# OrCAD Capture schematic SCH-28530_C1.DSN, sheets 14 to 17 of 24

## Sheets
14 14 EC1 PHY: size C
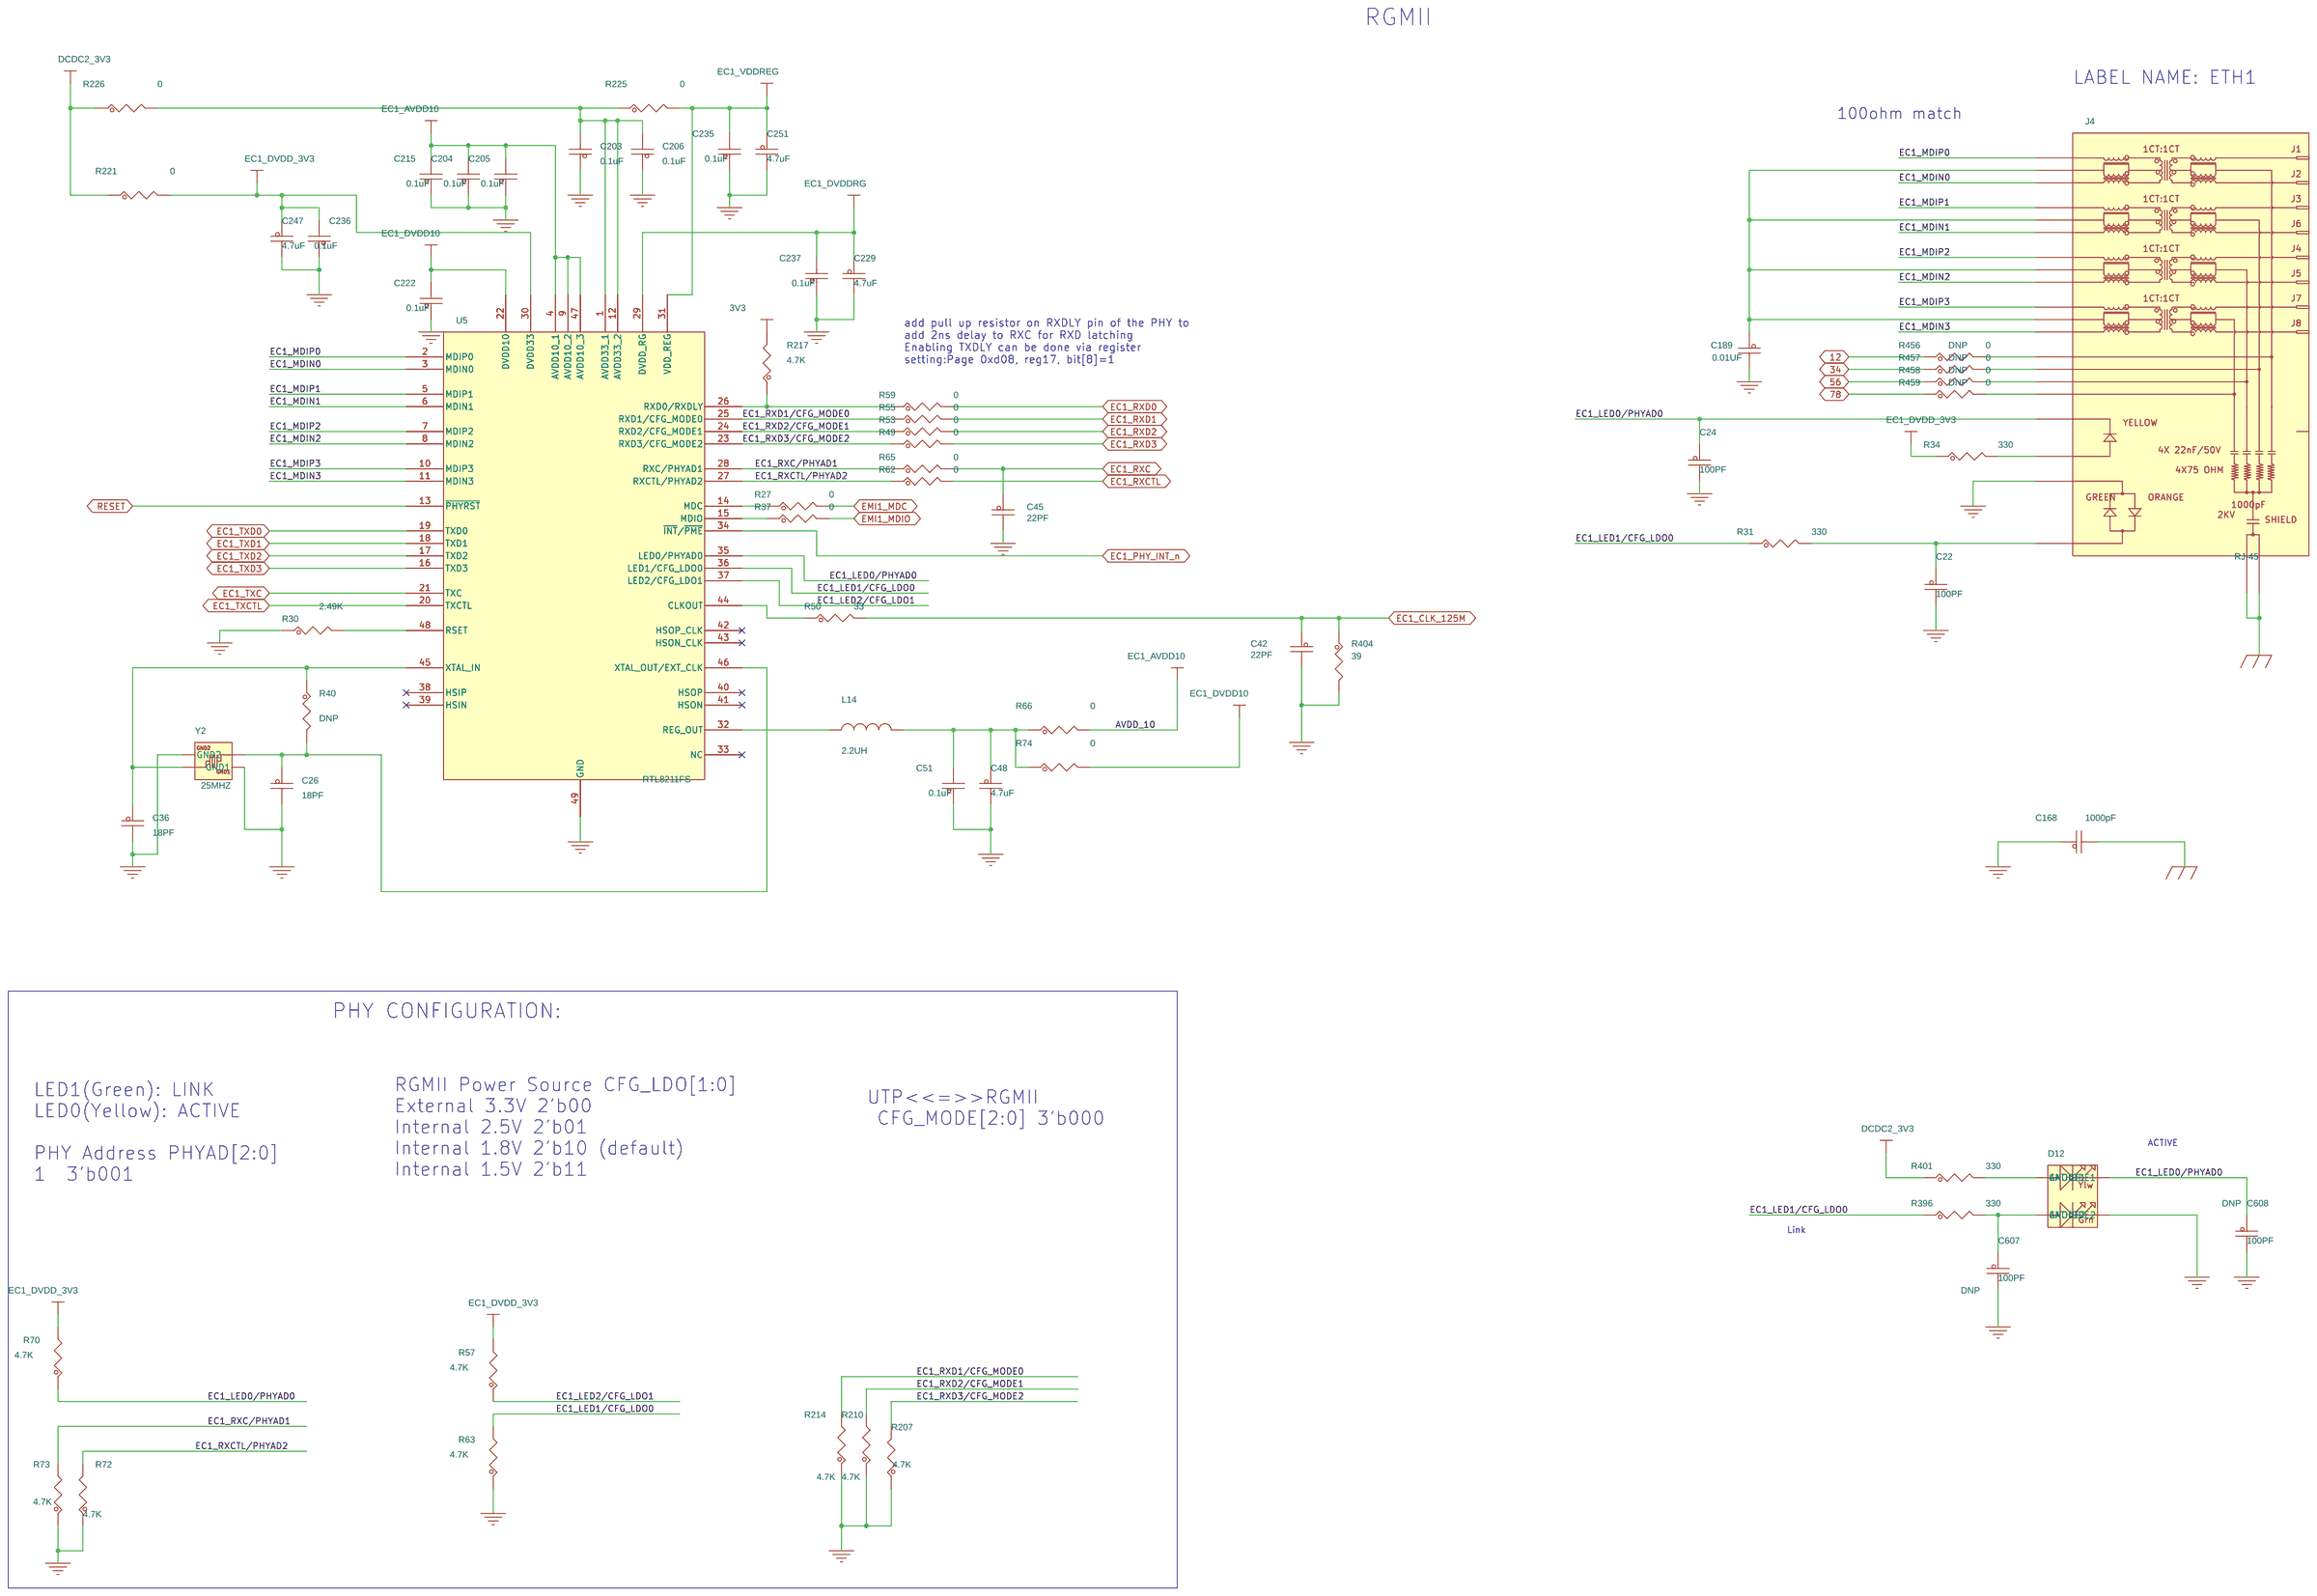
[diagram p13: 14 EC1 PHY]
15 15 SGMII PHY: size C
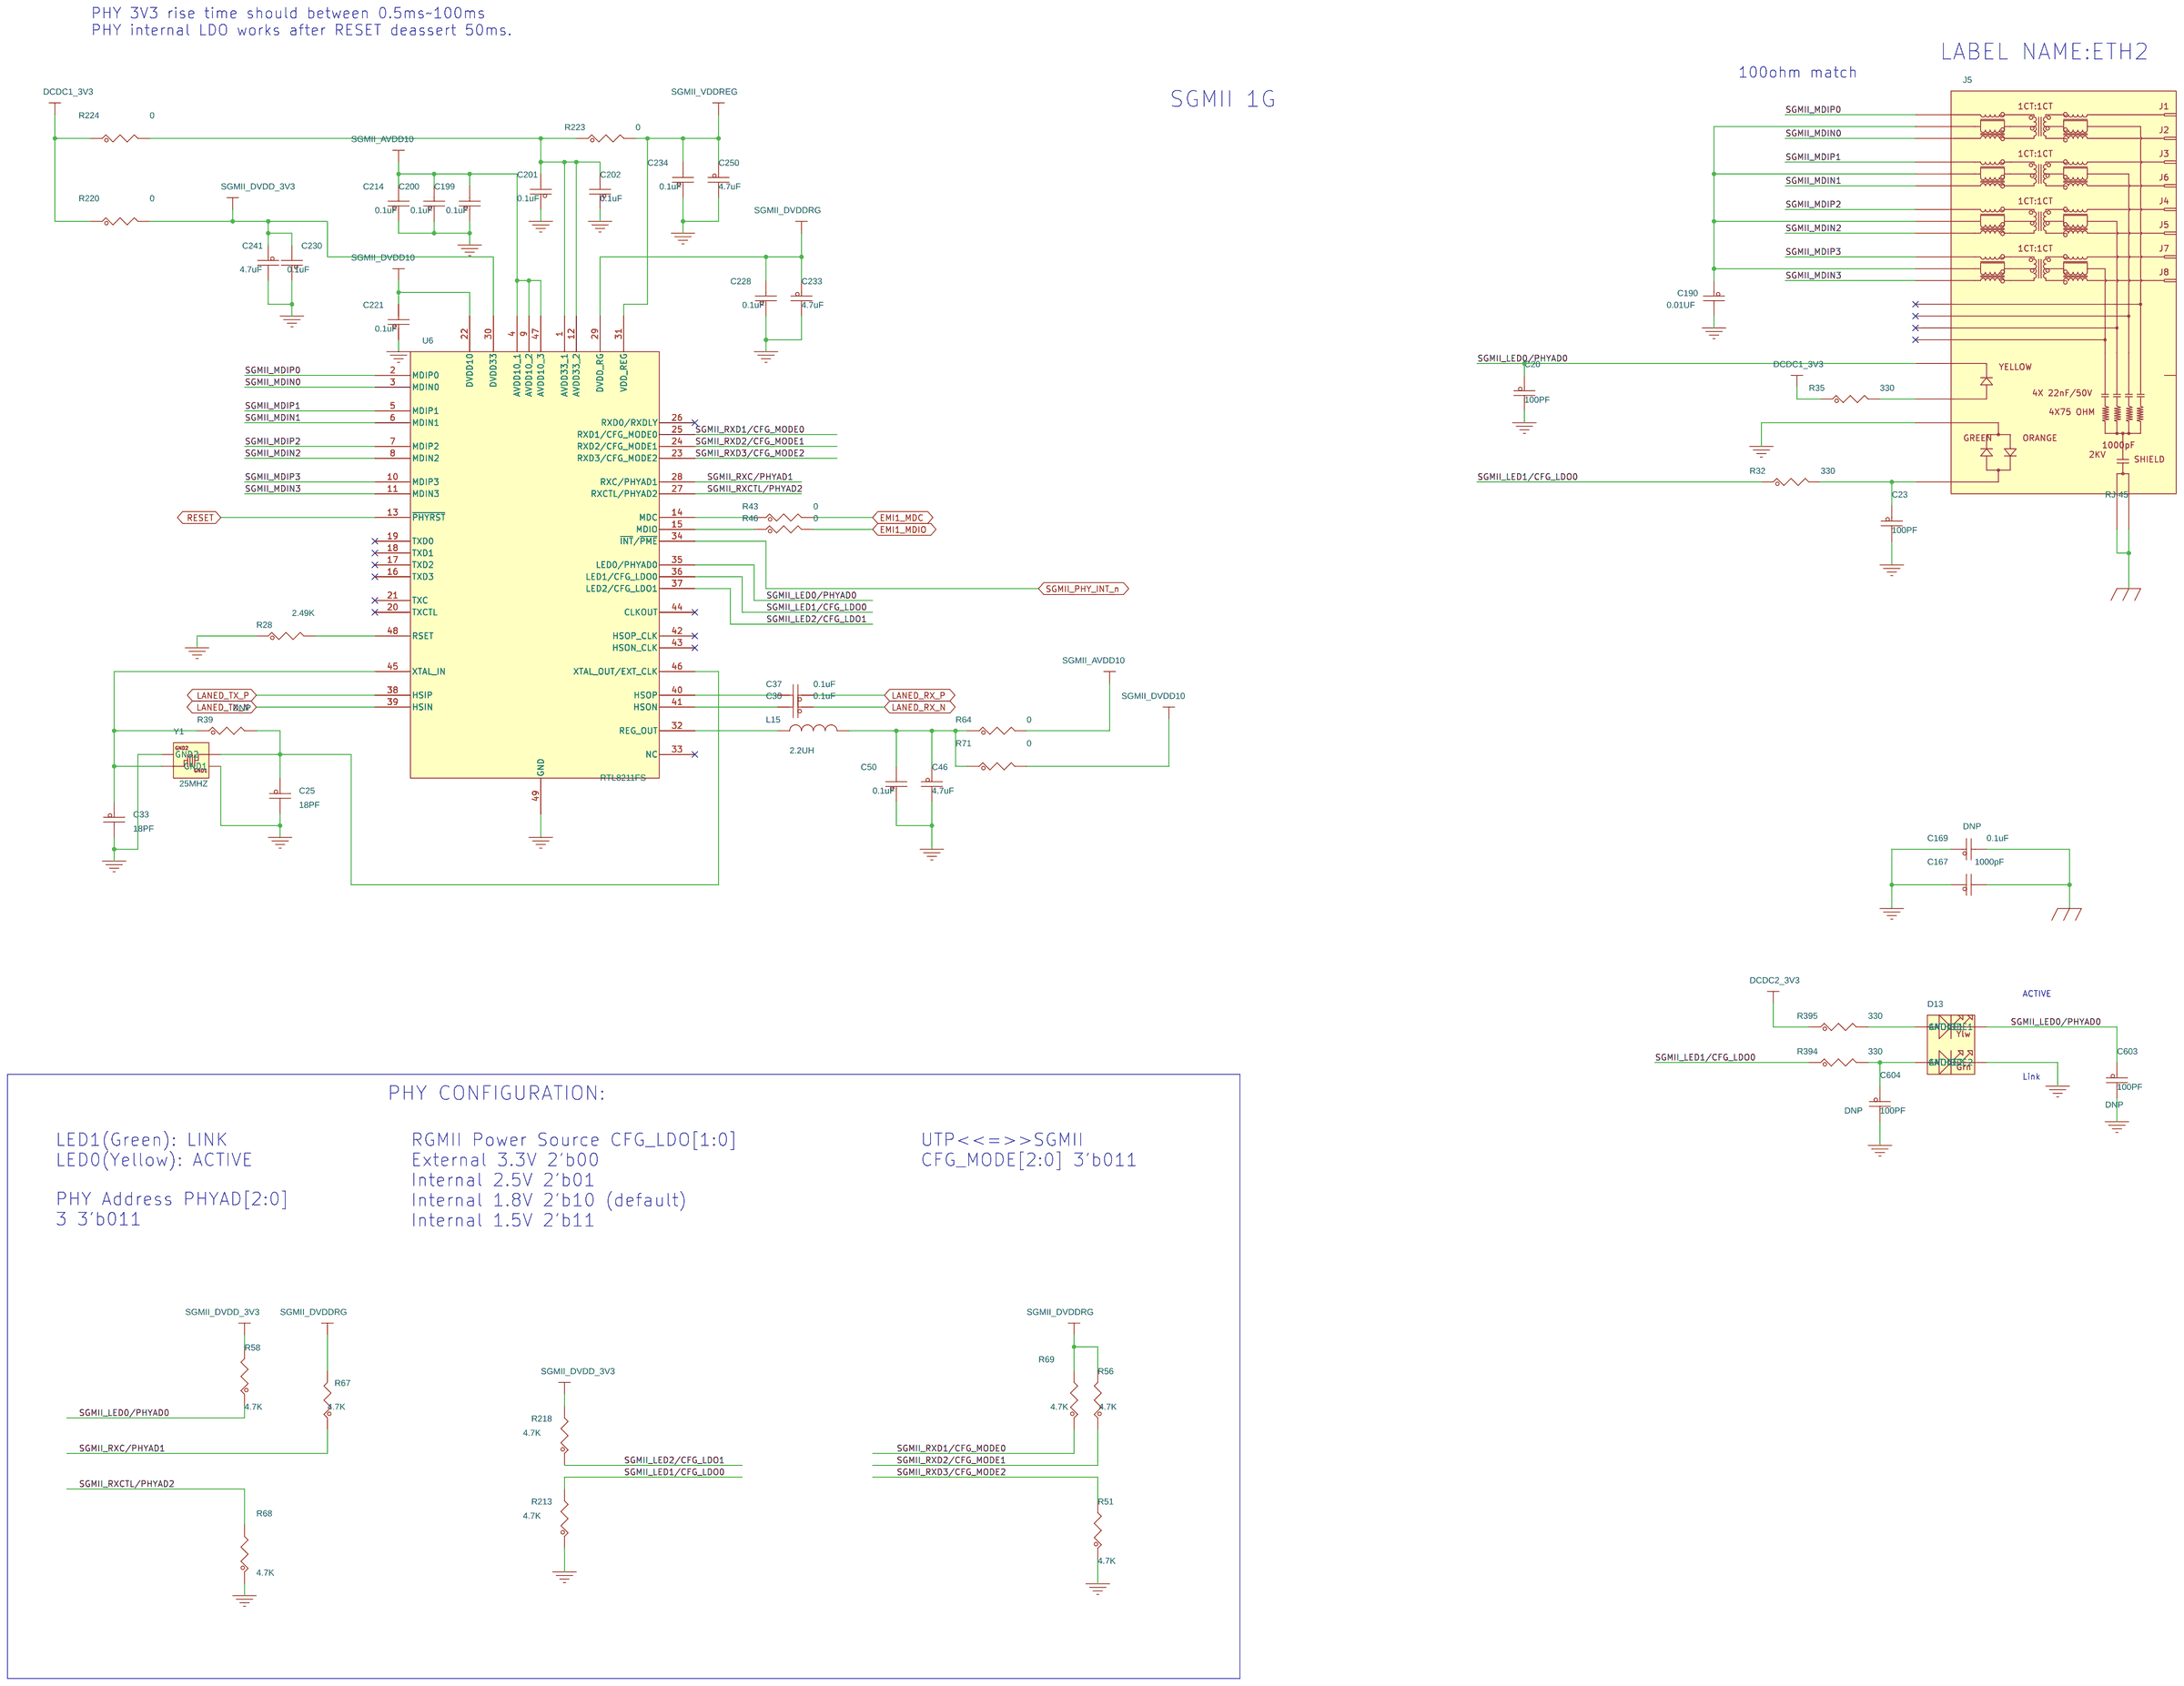
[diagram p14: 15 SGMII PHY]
16 16 AQR105: size C
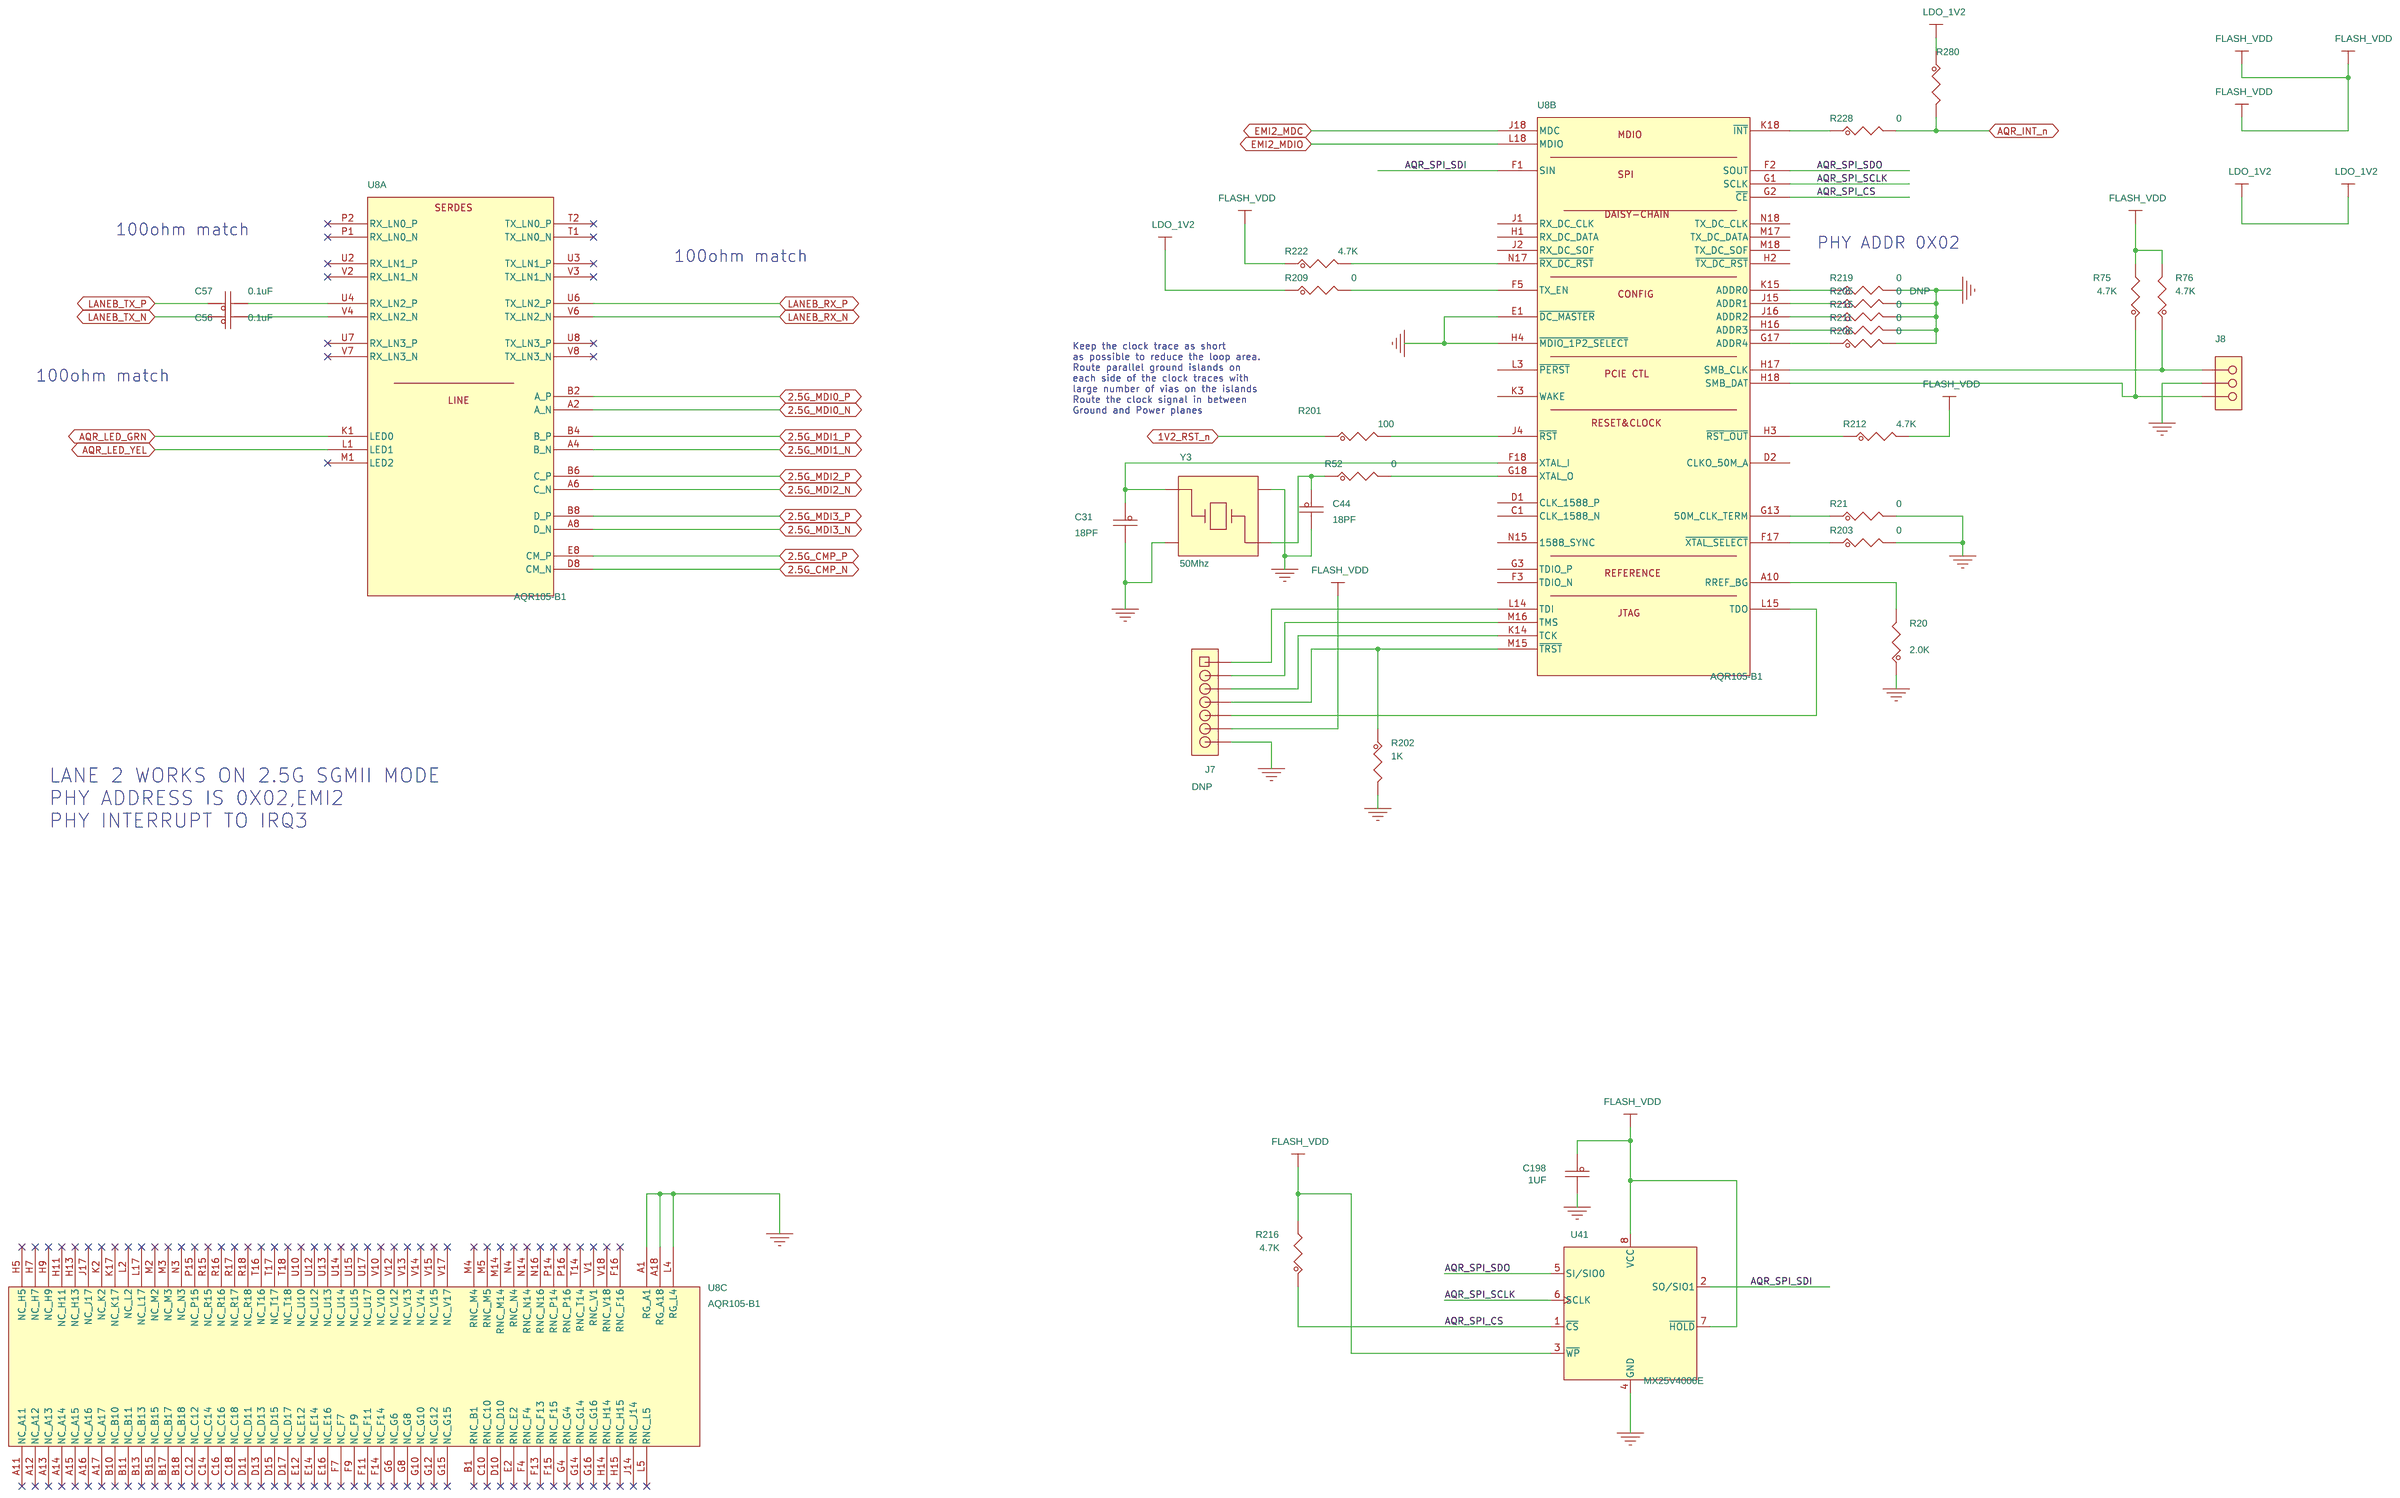
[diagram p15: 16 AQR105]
17 17 AQR105 POWER: size C
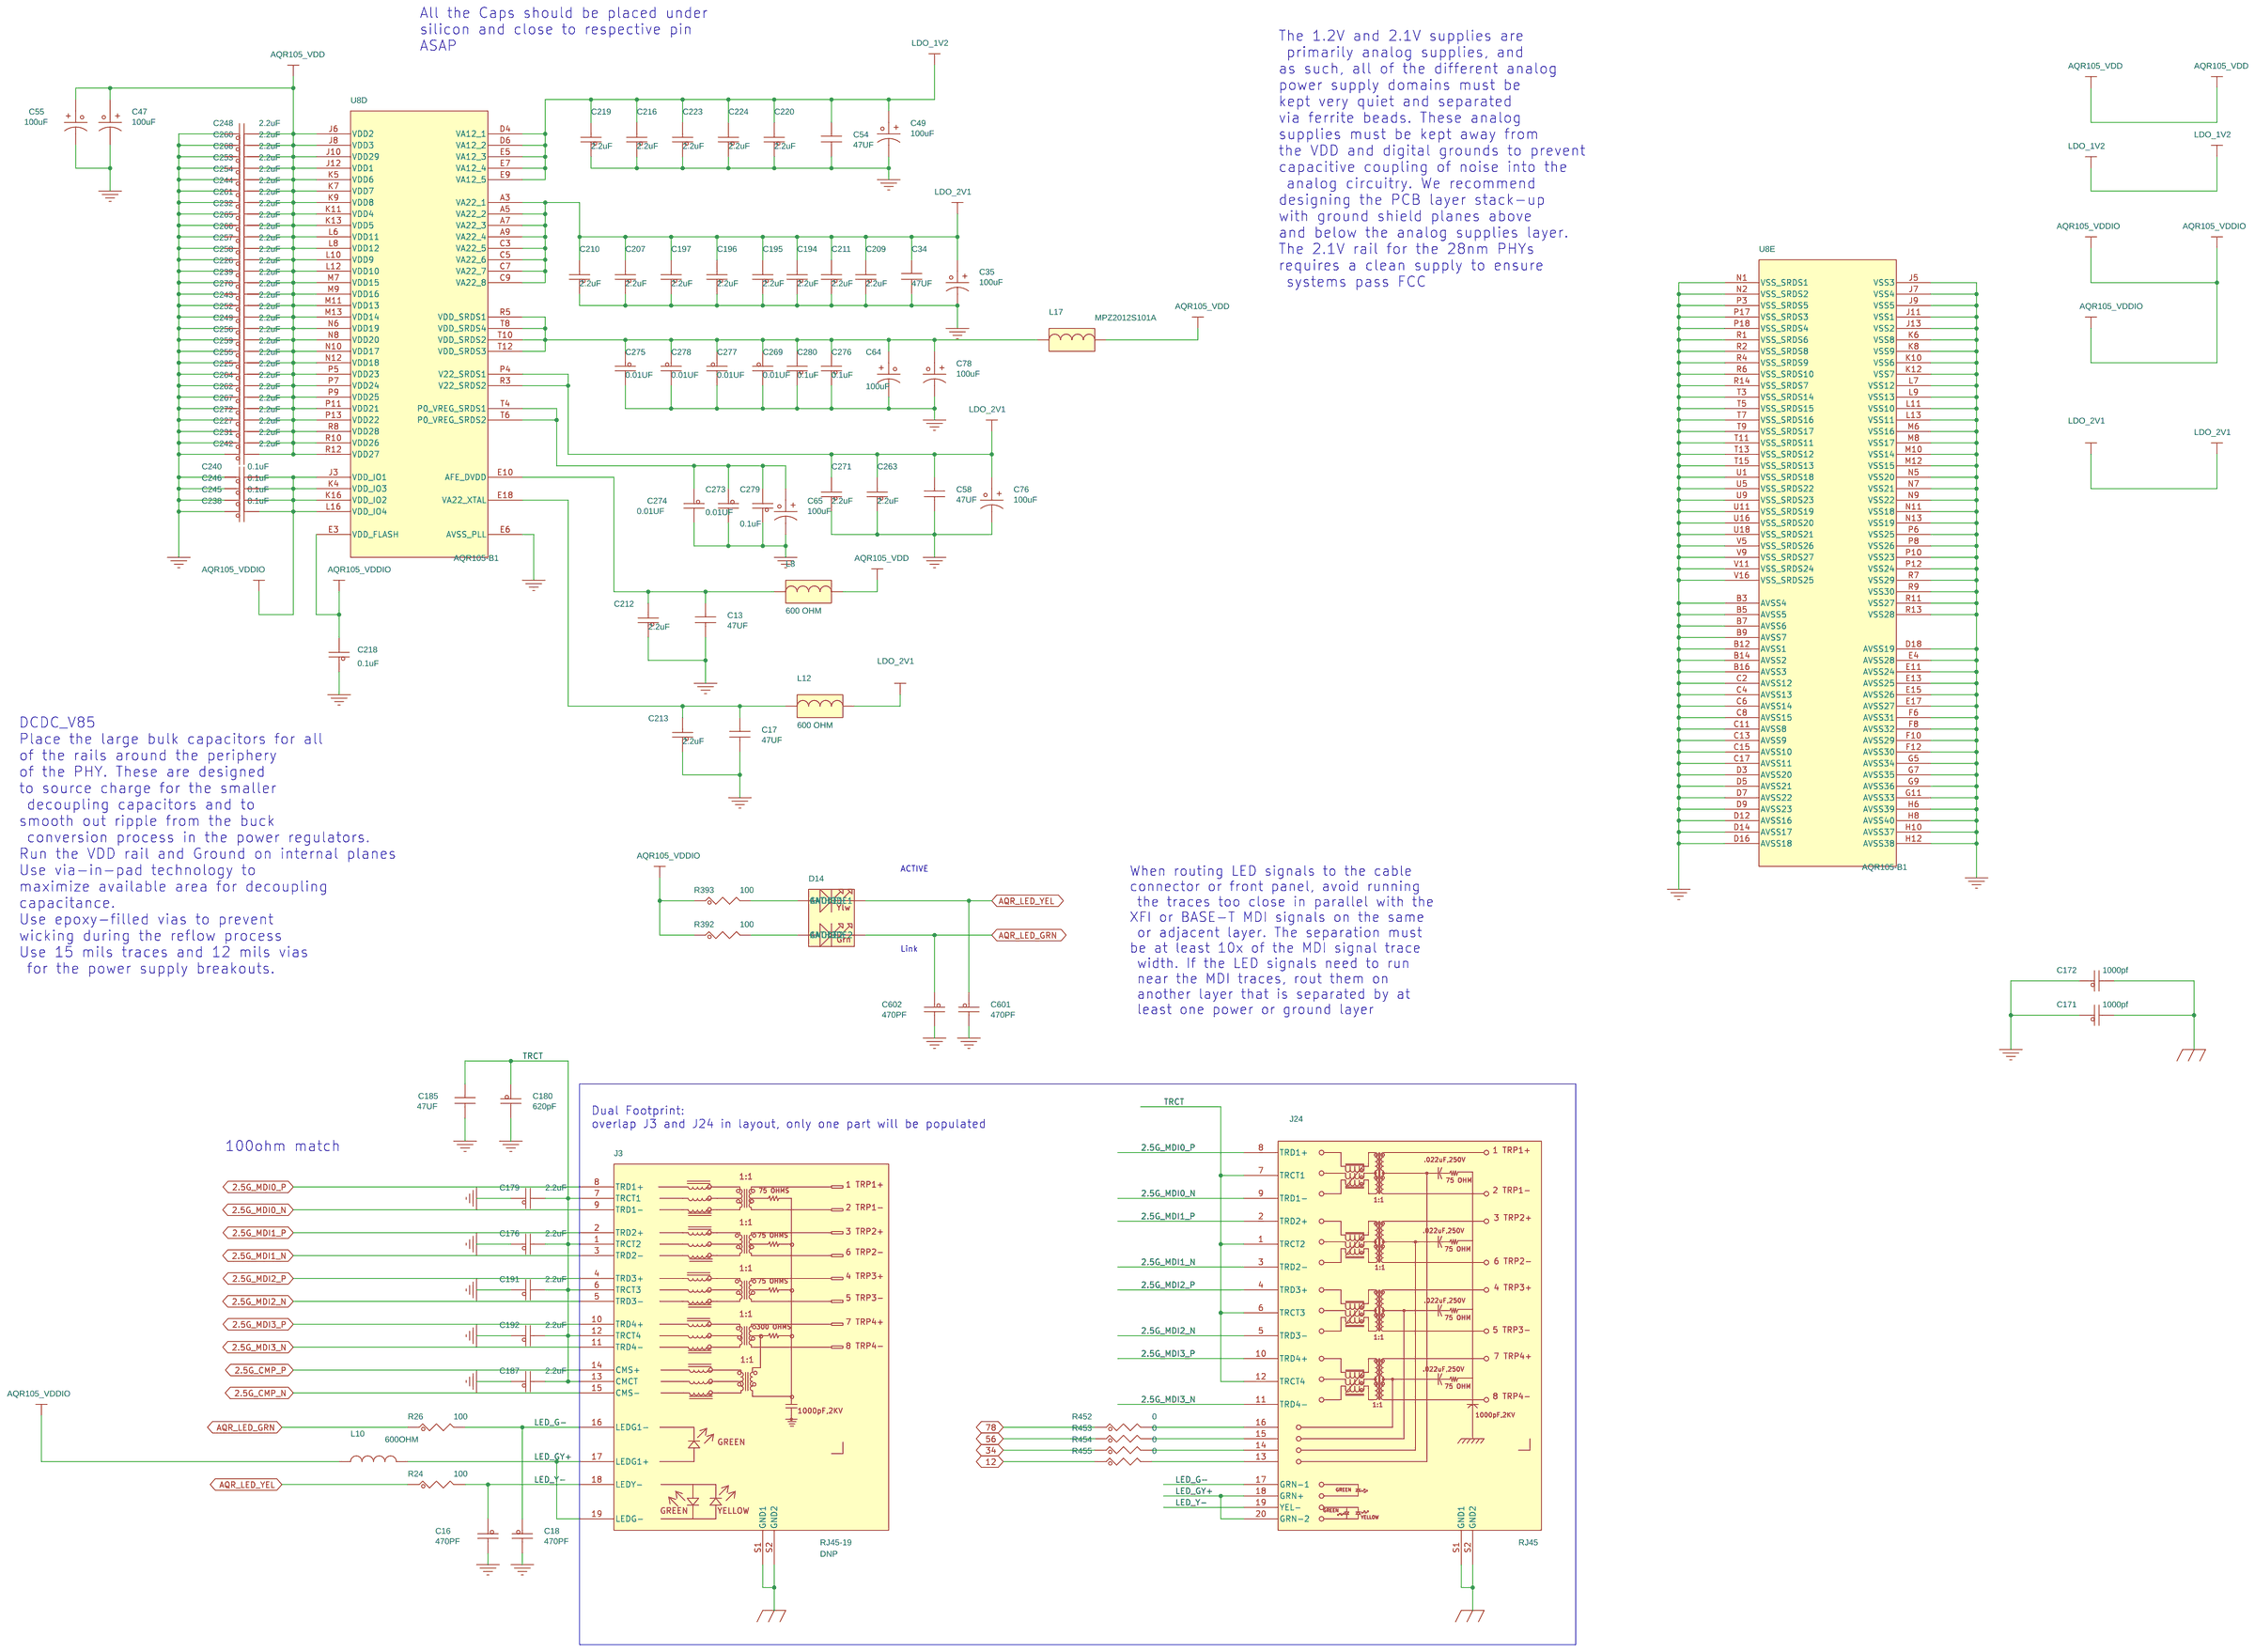
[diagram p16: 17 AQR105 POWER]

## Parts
sheet 14 EC1 PHY
C22  100PF  [CC0603_OV]
C24  100PF  [CC0603_OV]
C26  18PF  [CC0603_OV]
C36  18PF  [CC0603_OV]
C42  22PF  [CC0402_25]
C45  22PF  [CC0402_25]
C48  4.7uF  [CC0603_OV]
C51  0.1uF  [CC0402_25]
C168  1000pF  [cc1808_a]
C189  0.01UF  [CC0402_25]
C203  0.1uF  [CC0402_25]
C204  0.1uF  [CC0402_25]
C205  0.1uF  [CC0402_25]
C206  0.1uF  [CC0402_25]
C215  0.1uF  [CC0402_25]
C222  0.1uF  [CC0402_25]
C229  4.7uF  [CC0603_OV]
C235  0.1uF  [CC0402_25]
C236  0.1uF  [CC0402_25]
C237  0.1uF  [CC0402_25]
C247  4.7uF  [CC0603_OV]
C251  4.7uF  [CC0603_OV]
C607  100PF  [CC0603_OV]
C608  100PF  [CC0603_OV]
D12  LED GRN/YLW  [led4_2p54_9p3x4p5mm]
J4  RJ-45  [con_rj45_led_20_th]
L14  2.2UH  [IND2_4P3X4P3]
R27  0  [RC0603_OV]
R30  2.49K  [RC0603_OV]
R31  330  [RC0603_OV]
R34  330  [RC0603_OV]
R37  0  [RC0603_OV]
R40  1.0M  [RC0603_OV]
R49  0  [RC0402_25]
R50  33  [RC0603_OV]
R53  0  [RC0402_25]
R55  0  [RC0402_25]
R57  4.7K  [RC0603_OV]
R59  0  [RC0402_25]
R62  0  [RC0402_25]
R63  4.7K  [RC0603_OV]
R65  0  [RC0402_25]
R66  0  [RC0603_OV]
R70  4.7K  [RC0603_OV]
R72  4.7K  [RC0603_OV]
R73  4.7K  [RC0603_OV]
R74  0  [RC0603_OV]
R207  4.7K  [RC0603_OV]
R210  4.7K  [RC0603_OV]
R214  4.7K  [RC0603_OV]
R217  4.7K  [RC0603_OV]
R221  0  [RC0603_OV]
R225  0  [RC0603_OV]
R226  0  [RC0603_OV]
R396  330  [RC0603_OV]
R401  330  [RC0603_OV]
R404  39  [RC0402_25]
R456  0  [RC0603_OV]
R457  0  [RC0603_OV]
R458  0  [RC0603_OV]
R459  0  [RC0603_OV]
U5  RTL8211FS  [qfn_48_0p4_6x6mm]
Y2  25MHZ  [xtlosc4_3p2x2p5mm_sm]
sheet 15 SGMII PHY
C20  100PF  [CC0603_OV]
C23  100PF  [CC0603_OV]
C25  18PF  [CC0603_OV]
C30  0.1uF  [CC0402_25]
C33  18PF  [CC0603_OV]
C37  0.1uF  [CC0402_25]
C46  4.7uF  [CC0603_OV]
C50  0.1uF  [CC0402_25]
C167  1000pF  [cc1808_a]
C169  0.1uF  [cc1812]
C190  0.01UF  [CC0402_25]
C199  0.1uF  [CC0402_25]
C200  0.1uF  [CC0402_25]
C201  0.1uF  [CC0402_25]
C202  0.1uF  [CC0402_25]
C214  0.1uF  [CC0402_25]
C221  0.1uF  [CC0402_25]
C228  0.1uF  [CC0402_25]
C230  0.1uF  [CC0402_25]
C233  4.7uF  [CC0603_OV]
C234  0.1uF  [CC0402_25]
C241  4.7uF  [CC0603_OV]
C250  4.7uF  [CC0603_OV]
C603  100PF  [CC0603_OV]
C604  100PF  [CC0603_OV]
D13  LED GRN/YLW  [led4_2p54_9p3x4p5mm]
J5  RJ-45  [con_rj45_led_20_th]
L15  2.2UH  [IND2_4P3X4P3]
R28  2.49K  [RC0603_OV]
R32  330  [RC0603_OV]
R35  330  [RC0603_OV]
R39  1.0M  [RC0603_OV]
R43  0  [RC0603_OV]
R46  0  [RC0603_OV]
R51  4.7K  [RC0603_OV]
R56  4.7K  [RC0603_OV]
R58  4.7K  [RC0603_OV]
R64  0  [RC0603_OV]
R67  4.7K  [RC0603_OV]
R68  4.7K  [RC0603_OV]
R69  4.7K  [RC0603_OV]
R71  0  [RC0603_OV]
R213  4.7K  [RC0603_OV]
R218  4.7K  [RC0603_OV]
R220  0  [RC0603_OV]
R223  0  [RC0603_OV]
R224  0  [RC0603_OV]
R394  330  [RC0603_OV]
R395  330  [RC0603_OV]
U6  RTL8211FS  [qfn_48_0p4_6x6mm]
Y1  25MHZ  [xtlosc4_3p2x2p5mm_sm]
sheet 16 AQR105
C31  18PF  [CC0603_OV]
C44  18PF  [CC0603_OV]
C56  0.1uF  [CC0402_25]
C57  0.1uF  [CC0402_25]
C198  1UF  [CC0402_25]
J7  HDR_1X7  [JUMP1X7-6040]
J8  HDR TH 1X3  [HDR103]
R20  2.0K  [RC0603_OV]
R21  0  [RC0603_OV]
R52  0  [RC0603_OV]
R75  4.7K  [RC0603_OV]
R76  4.7K  [RC0603_OV]
R201  100  [RC0603_OV]
R202  1K  [RC0603_OV]
R203  0  [RC0603_OV]
R205  0  [RC0603_OV]
R206  0  [RC0603_OV]
R209  0  [RC0603_OV]
R211  0  [RC0603_OV]
R212  4.7K  [RC0603_OV]
R215  0  [RC0603_OV]
R216  4.7K  [RC0603_OV]
R219  0  [RC0603_OV]
R222  4.7K  [RC0603_OV]
R228  0  [RC0603_OV]
R280  4.7K  [RC0402_25]
U41  MX25V4006E  [SO8_1p27_4x5]
Y3  50Mhz  [xtal4_3p3x2p6_sm_fl]
sheet 17 AQR105 POWER
C13  47UF  [CC1210]
C16  470PF  [CC0603_OV]
C17  47UF  [CC1210]
C18  470PF  [CC0603_OV]
C34  47UF  [CC1210]
C35  100uF  [cce63x55]
C47  100uF  [cce63x55]
C49  100uF  [cce63x55]
C54  47UF  [CC1210]
C55  100uF  [cce63x55]
C58  47UF  [CC1210]
C64  100uF  [cce63x55]
C65  100uF  [cce63x55]
C76  100uF  [cce63x55]
C78  100uF  [cce63x55]
C171  1000pf  [CC1210]
C172  1000pf  [CC1210]
C176  2.2uF  [CC0402_25]
C179  2.2uF  [CC0402_25]
C180  620pF  [CC0402_25]
C185  47UF  [CC1210]
C187  2.2uF  [CC0402_25]
C191  2.2uF  [CC0402_25]
C192  2.2uF  [CC0402_25]
C194  2.2uF  [CC0402_25]
C195  2.2uF  [CC0402_25]
C196  2.2uF  [CC0402_25]
C197  2.2uF  [CC0402_25]
C207  2.2uF  [CC0402_25]
C209  2.2uF  [CC0402_25]
C210  2.2uF  [CC0402_25]
C211  2.2uF  [CC0402_25]
C212  2.2uF  [CC0402_25]
C213  2.2uF  [CC0402_25]
C216  2.2uF  [CC0402_25]
C218  0.1uF  [CC0402_25]
C219  2.2uF  [CC0402_25]
C220  2.2uF  [CC0402_25]
C223  2.2uF  [CC0402_25]
C224  2.2uF  [CC0402_25]
C225  2.2uF  [CC0402_25]
C226  2.2uF  [CC0402_25]
C227  2.2uF  [CC0402_25]
C231  2.2uF  [CC0402_25]
C232  2.2uF  [CC0402_25]
C238  0.1uF  [CC0402_25]
C239  2.2uF  [CC0402_25]
C240  0.1uF  [CC0402_25]
C242  2.2uF  [CC0402_25]
C243  2.2uF  [CC0402_25]
C244  2.2uF  [CC0402_25]
C245  0.1uF  [CC0402_25]
C246  0.1uF  [CC0402_25]
C248  2.2uF  [CC0402_25]
C249  2.2uF  [CC0402_25]
C252  2.2uF  [CC0402_25]
C253  2.2uF  [CC0402_25]
C254  2.2uF  [CC0402_25]
C255  2.2uF  [CC0402_25]
C256  2.2uF  [CC0402_25]
C257  2.2uF  [CC0402_25]
C258  2.2uF  [CC0402_25]
C259  2.2uF  [CC0402_25]
C260  2.2uF  [CC0402_25]
C261  2.2uF  [CC0402_25]
C262  2.2uF  [CC0402_25]
C263  2.2uF  [CC0402_25]
C264  2.2uF  [CC0402_25]
C265  2.2uF  [CC0402_25]
C266  2.2uF  [CC0402_25]
C267  2.2uF  [CC0402_25]
C268  2.2uF  [CC0402_25]
C269  0.01UF  [CC0402_25]
C270  2.2uF  [CC0402_25]
C271  2.2uF  [CC0402_25]
C272  2.2uF  [CC0402_25]
C273  0.01UF  [CC0402_25]
C274  0.01UF  [CC0402_25]
C275  0.01UF  [CC0402_25]
C276  0.1uF  [CC0402_25]
C277  0.01UF  [CC0402_25]
C278  0.01UF  [CC0402_25]
C279  0.1uF  [CC0402_25]
C280  0.1uF  [CC0402_25]
C601  470PF  [CC0603_OV]
C602  470PF  [CC0603_OV]
D14  LED GRN/YLW  [led4_2p54_9p3x4p5mm]
J3  RJ45-19  [con19_rj-45_led_80mil_th_ra]
J24  RJ45  [con16_rj45_led_80_th_ra]
L8  600 OHM  [IND_0805]
L10  600OHM  [IND_0603]
L12  600 OHM  [IND_0805]
L17  MPZ2012S101A  [IND_0805]
R24  100  [RC0603_OV]
R26  100  [RC0603_OV]
R392  100  [RC0603_OV]
R393  100  [RC0603_OV]
R452  0  [RC0603_OV]
R453  0  [RC0603_OV]
R454  0  [RC0603_OV]
R455  0  [RC0603_OV]
U8  AQR105-B1  [bga324_1mm_19x19mm_c019s]  (sections A,B,C,D,E)

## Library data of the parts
C20 C22-C24 = CAP_NP: CAP CER 100PF 25V 10% C0G 0603; AGILE_PN: 150-30171; CAD_APPROVED: Yes; FPLIST: CC0603_OV,CC0603,0603_CC; HEIGHT: 0.86MM; MFG_NAME01: AVX; MFG_PN01: 06033A101KAT2A; ROHS: Yes; Tolerance: 10%; VOLTAGE: 25V
C25 C26 C31 C33 C36 C44 = CAP_NP: CAP CER 18PF 50V 5% C0G 0603; AGILE_PN: 150-75116; CAD_APPROVED: Yes; FPLIST: CC0603_OV,CC0603,0603_CC; HEIGHT: 0.90MM; MFG_NAME01: YAGEO AMERICA; MFG_PN01: CC0603JRNPO9BN180; ROHS: Yes; SIGNAL_MODEL: CAP_NP_CC0402_25_0_55MM_150_762_0_01uF; Tolerance: 5%; VOLTAGE: 50V
C42 C45 = CAP_NP: CAP CER 22PF 50V 5% C0G 0402; AGILE_PN: 150-75266; CAD_APPROVED: Yes; FPLIST: CC0402_25,CC0402_HD,0402_CC; HEIGHT: 0.635MM; MFG_NAME01: AVX; MFG_PN01: 04025A220JAT2A; ROHS: Yes; Tolerance: 5%; VOLTAGE: 50V
C46 C48 C229 C233 C241 C247 C250 C251 = CAP_NP: CAP CER 4.7UF 10V 10% X5R 0603; AGILE_PN: 150-77975; CAD_APPROVED: Yes; FPLIST: CC0603_OV,CC0603,0603_CC; HEIGHT: 0.9MM; MFG_NAME01: TAIYO YUDEN; MFG_PN01: LMK107BJ475KA-T; ROHS: Yes; Tolerance: 10%; VOLTAGE: 10V
C30 C37 C50 C51 C199-C206 C214 C215 C221 C222 C228 C230 C234-C237 = CAP_NP: CAP CER 0.1UF 25V 10% X5R 0402; AGILE_PN: 150-78633; CAD_APPROVED: Yes; FPLIST: CC0402_25,CC0402_HD,0402_CC; HEIGHT: 0.55MM; MFG_NAME01: YAGEO AMERICA; MFG_PN01: CC0402KRX5R8BB104; ROHS: Yes; SIGNAL_MODEL: DEFAULT_CAPACITOR_1e+07pF_2_1; Tolerance: 10%; VOLTAGE: 25V
C167 C168 = CAP_NP: CAP CER 1000pF 3000V 10% X7R 1808; AGILE_PN: 150-78761; CAD_APPROVED: Yes; HEIGHT: 2.2MM; MFG_NAME01: YAGEO AMERICA; MFG_PN01: CC1808KKX7REBB102; ROHS: Yes; SIGNAL_MODEL: DEFAULT_CAPACITOR_1000pF_2_1; Tolerance: 10%; VOLTAGE: 3000V
C189 C190 C269 C273-C275 C277 C278 = CAP_NP: CAP CER 0.01UF 16V 20% X7R 0402; AGILE_PN: 150-30082; CAD_APPROVED: Yes; FPLIST: CC0402_25,CC0402_HD,0402_CC; HEIGHT: 0.56MM; MFG_NAME01: AVX; MFG_PN01: 0402YC103MAT2A; ROHS: Yes; Tolerance: 20%; VOLTAGE: 16V
C603 C604 C607 C608 = CAP_NP: CAP CER 100PF 25V 10% C0G 0603; AGILE_PN: 150-30171; ASSY_OPT: DNP; CAD_APPROVED: Yes; FPLIST: CC0603_OV,CC0603,0603_CC; HEIGHT: 0.86MM; MFG_NAME01: AVX; MFG_PN01: 06033A101KAT2A; ROHS: Yes; Tolerance: 10%; VOLTAGE: 25V
D12-D14 = LED_DUAL_SEP2_YG: LED GRN/YEL DUAL 25/30MA TH; AGILE_PN: 370-76480; CAD_APPROVED: Yes; HEIGHT: 9.9MM; MFG_NAME01: KINGBRIGHT; MFG_PN01: L-7104EB/1G1YD-SH; ROHS: Yes
J4 J5 = RJ45_LED_22P: CON 20 RJ-45 RA SHLD TH G/Y LEDS 80MIL SP 630H AU 125L; AGILE_PN: 210-80719; CAD_APPROVED: Yes; HEIGHT: 16.02 MM; MFG_NAME01: WURTH ELEKTRONIK EISOS GMBH & CO. KG; MFG_PN01: 7499511611A; ROHS: Yes
L14 L15 = INDUCTOR: IND PWR 2.2UH@100KHZ 0.03 OHM 2.95A 30% SMT; AGILE_PN: 180-77799; CAD_APPROVED: Yes; HEIGHT: 3.0 MM; MFG_NAME01: Shenzhen Sunlord Electronics Co., Ltd; MFG_PN01: SWPA4030S2R2NT; PART_TYPE: INDUCTOR\POWER; ROHS: Yes; Tolerance: 30%
R21 R27 R37 R43 R46 R52 R64 R66 R71 R74 R203 R206 R209 R211 R215 R219-R221 R223-R226 R228 R452-R455 = RES: RES MF ZERO OHM 1/10W -- 0603; AGILE_PN: 470-80866; FPLIST: RC0603_OV,RC0603,R603-X2,0603_CC; HEIGHT: 0.6MM; MFG_NAME01: BOURNS; MFG_PN01: CR0603J/000ELF; ROHS: Yes
R28 R30 = RES: RES MF 2.49K 1/10W 1% 0603; AGILE_PN: 470-75560; CAD_APPROVED: Yes; FPLIST: RC0603_OV,RC0603,0603_CC; HEIGHT: 0.6MM; MFG_NAME01: KOA SPEER; MFG_PN01: RK73H1JTTD2491F; ROHS: Yes; Tolerance: 1%
R31 R32 R34 R35 R394-R396 R401 = RES: RES MF 330 OHM 1/10W 1% 0603; AGILE_PN: 470-75512; CAD_APPROVED: Yes; FPLIST: RC0603_OV,RC0603,0603_CC; HEIGHT: 0.55 MM; MFG_NAME01: KOA SPEER; MFG_PN01: RK73H1JTTD3300F; ROHS: Yes; Tolerance: 1%
R39 R40 = RES: RES MF 1.0M 1/10W 1% 0603; AGILE_PN: 470-76249; ASSY_OPT: DNP; CAD_APPROVED: Yes; FPLIST: RC0603_OV,RC0603,0603_CC; Function: SATA; HEIGHT: 0.6mm; MFG_NAME01: WALSIN TECHNOLOGY CORP.; MFG_PN01: WR06X1004FTL; ROHS: Yes; SIGNAL_MODEL: DEFAULT_RESISTOR_33OHM_2_1; Tolerance: 1%
R49 R53 R55 R59 R62 R65 = RES: RES MF ZERO OHM 1/16W 5% 0402; AGILE_PN: 470-75394; CAD_APPROVED: Yes; FPLIST: RC0402_25,RC0402_HD,RC0402_X2,0402_CC; HEIGHT: 0.45 MM; MFG_NAME01: ROHM; MFG_PN01: MCR01MZPJ000; ROHS: Yes; SIGNAL_MODEL: RES_RC0402_25_DISCRETE_470-7539_0; Tolerance: 5%
R50 = RES: RES MF 33 OHM 1/10W 1% 0603; AGILE_PN: 470-75389; CAD_APPROVED: Yes; FPLIST: RC0603_OV,RC0603,0603_CC; HEIGHT: 0.55 mm; MFG_NAME01: KOA SPEER; MFG_PN01: RK73H1JTTD33R0F; ROHS: Yes; Tolerance: 1%
R51 R56-R58 R63 R67-R70 R72 R73 R75 R76 R207 R210 R212-R214 R216-R218 R222 = RES: RES MF 4.7K 1/10W 5% 0603; AGILE_PN: 470-75414; CAD_APPROVED: Yes; FPLIST: RC0603_OV,RC0603,0603_CC; HEIGHT: 0.55 MM; MFG_NAME01: VISHAY INTERTECHNOLOGY; MFG_PN01: CRCW06034K70JNEA; ROHS: Yes; Tolerance: 5%
R404 = RES: RES MF 39 OHM 1/16W 1% 0402; AGILE_PN: 470-30699; CAD_APPROVED: Yes; FPLIST: RC0402_25,RC0402_HD,0402_CC; HEIGHT: 0.40 MM; MFG_NAME01: KOA SPEER; MFG_PN01: RK73H1ETTP39R0F; ROHS: Yes; Tolerance: 1%
R205 R456-R459 = RES: RES MF ZERO OHM 1/10W -- 0603; AGILE_PN: 470-80866; ASSY_OPT: DNP; FPLIST: RC0603_OV,RC0603,R603-X2,0603_CC; HEIGHT: 0.6MM; MFG_NAME01: BOURNS; MFG_PN01: CR0603J/000ELF; ROHS: Yes
U5 U6 = RTL8211_48P: IC XCVR ETH 10/100/1000MBPS RGMII 3.3/2.5/1.8/1.5V QFN48; AGILE_PN: 315-80402; CAD_APPROVED: Yes; HEIGHT: 1 MM; MFG_NAME01: Realtek Semiconductor; MFG_PN01: RTL8211FS-CG; ROHS: Yes
Y1 Y2 = CRYSTAL_JXS63: XTAL 25MHZ 18PF -- 3.2X2.5MM SMT; AGILE_PN: 230-77713; CAD_APPROVED: Yes; HEIGHT: 0.6MM; MFG_NAME01: CITIZEN; MFG_PN01: CS325 25.000MABJ-UT; ROHS: Yes
C169 = CAP_NP: CAP CER 0.1uF 630V 10% X7R 1812; AGILE_PN: 150-79229; ASSY_OPT: DNP; CAD_APPROVED: Yes; HEIGHT: 2 MM; MFG_NAME01: Murata; MFG_PN01: GRJ43DR72J104KWJ1L; ROHS: Yes; VOLTAGE: 630V
C56 C57 C218 C238 C240 C245 C246 C276 C279 C280 = CAP_NP: CAP CER 0.1UF 16V 10% X5R 0402; AGILE_PN: 150-75663; CAD_APPROVED: Yes; FPLIST: CC0402_25,CC0402_HD,0402_CC; HEIGHT: 0.55MM; MFG_NAME01: TDK; MFG_PN01: C1005X5R1C104K; ROHS: Yes; Tolerance: 10%; VOLTAGE: 16V
C198 = CAP_NP: CAP CER 1UF 6.3V 20% X5R 0402; AGILE_PN: 150-78002; CAD_APPROVED: Yes; FPLIST: CC0402_25,CC0402_HD,0402_CC; HEIGHT: 0.55MM; MFG_NAME01: MURATA; MFG_PN01: GRM155R60J105ME19D; ROHS: Yes; Tolerance: 20%; VOLTAGE: 6.3V
J7 = HDR-1X7: HDR 1X7 TH 100MIL SP  330H AU; AGILE_PN: 210-75690; ASSY_OPT: DNP; CAD_APPROVED: Yes; HEIGHT: 8.382 MM; MFG_NAME01: SAMTEC; MFG_PN01: TSW-107-07-G-S; ROHS: Yes
J8 = CONN_HDR_3X1: HDR 1X3 TH 100MIL SP 339H AU 100L; AGILE_PN: 210-75726; CAD_APPROVED: Yes; HEIGHT: 8.65MM; MFG_NAME01: SAMTEC; MFG_PN01: TSW-103-07-G-S; ROHS: Yes
R20 = RES: RES MF 2.00K 1/10W 1% 0603; AGILE_PN: 470-75802; CAD_APPROVED: Yes; FPLIST: RC0603_OV,RC0603,0603_CC; HEIGHT: 0.55 MM; MFG_NAME01: ROHM; MFG_PN01: MCR03EZPFX2001; ROHS: Yes; Tolerance: 1%
R24 R26 R201 R392 R393 = RES: RES MF 100 OHM 1/10W 5% 0603; AGILE_PN: 470-75411; CAD_APPROVED: YES; FPLIST: RC0603_OV,RC0603,0603_CC; HEIGHT: 0.55MM; MFG_NAME01: BOURNS; MFG_PN01: CR0603-JW-101ELF; ROHS: Yes; Tolerance: 5%
R202 = RES: RES MF 1K 1/10W 1% 0603; AGILE_PN: 470-80784; CAD_APPROVED: Yes; FPLIST: RC0603_OV,RC0603,0603_CC; HEIGHT: 0.55MM; MFG_NAME01: VIKING TECH CORPORATION; MFG_PN01: AR03FTNX1001; ROHS: Yes; Tolerance: 1%
R280 = RES: RES MF 4.7K 1/16W 5% 0402; AGILE_PN: 470-75626; CAD_APPROVED: Yes; FPLIST: RC0402_25,RC0402_HD,0402_CC; Function: UART; HEIGHT: 0.41mm; MFG_NAME01: KOA SPEER; MFG_PN01: RK73B1ETTP472J; ROHS: Yes; SIGNAL_MODEL: DEFAULT_RESISTOR_4700OHM_2_1; TOL: 5%; Tolerance: 5%
U41 = MX25V4006E_8P: IC MEM FLASH 4MBIT 75MHz 2.5V SO8; AGILE_PN: 342-00610; CAD_APPROVED: Yes; HEIGHT: 1.75MM; MFG_NAME01: MACRONIX INTERNATIONAL CO., LTD; MFG_PN01: MX25V4006EM1I-13G; ROHS: Yes
Y3 = XTAL_13Y: XTAL 50MHZ 18pF 20PPM SMD; AGILE_PN: 230-78026; CAD_APPROVED: Yes; HEIGHT: 0.75MM; MFG_NAME01: PERICOM SEMICONDUCTOR; MFG_PN01: FL5000014; ROHS: Yes
C13 C17 C34 C54 C58 C185 = MOT_CAP: CAP CER 47UF 16V 10% X5R 1210; AGILE_PN: 150-75908; CAD_APPROVED: Yes; FPLIST: CC1210,1210_CC; HEIGHT: 2.7 mm; MFG_NAME01: MURATA; MFG_PN01: GRM32ER61C476KE15L; ROHS: Yes; Tolerance: 10%; VOLTAGE: 16V
C16 C18 C601 C602 = CAP_NP: CAP CER 470PF 50V 10% X7R 0603; AGILE_PN: 150-75277; CAD_APPROVED: YES; FPLIST: CC0603_OV,CC0603,0603_CC; HEIGHT: 0.9652MM; MFG_NAME01: AVX; MFG_PN01: 06035C471KAT2A; ROHS: Yes; Tolerance: 10%; VOLTAGE: 50V
C35 C47 C49 C55 C64 C65 C76 C78 = CAP_POL: CAP ALEL 100uF 16V 20% -- SMD; AGILE_PN: 150-78723; CAD_APPROVED: Yes; HEIGHT: 5.5MM; MFG_NAME01: LELON ELECTRONICS CORP; MFG_PN01: VE-101M1CTR-0605; ROHS: Yes; Tolerance: 20%; VOLTAGE: 16V
C171 C172 = CAP_NP: CAP CER 1000PF 2KV 10% X7R 1210; AGILE_PN: 150-75027; CAD_APPROVED: Yes; FPLIST: CC1210,1210_CC; HEIGHT: 1.7MM; MFG_NAME01: AVX; MFG_PN01: 1210GC102KAT1A; ROHS: Yes; Tolerance: 10%; VOLTAGE: 2KV
C176 C179 C187 C191 C192 C194-C197 C207 C209-C213 C216 C219 C220 C223-C227 C231 C232 C239 C242-C244 C248 C249 C252-C268 C270-C272 = CAP_NP: CAP CER 2.2uF 10V 10% X5R 0402; AGILE_PN: 150-78974; CAD_APPROVED: Yes; FPLIST: CC0402_25,CC0402_HD,0402_CC; HEIGHT: 0.55 MM; MFG_NAME01: TDK; MFG_PN01: C1005X5R1A225K; ROHS: Yes; Tolerance: 10%; VOLTAGE: 10V
C180 = CAP_NP: CAP CER 620pF 50V 5% C0G 0402; AGILE_PN: 150-79448; CAD_APPROVED: Yes; FPLIST: CC0402_25,CC0402_HD,0402_CC; HEIGHT: 0.55MM; MFG_NAME01: MURATA; MFG_PN01: GRM1555C1H621JA01D; ROHS: Yes; Tolerance: 5%; VOLTAGE: 50V
J3 = CON_RJ45_19P: CON 19 RA RJ-45 10GBASE-T TH 80MIL SP 547H AU 125L; AGILE_PN: 210-80700; ASSY_OPT: DNP; CAD_APPROVED: Yes; HEIGHT: 13.89 MM; MFG_NAME01: PULSE ELECTRONICS; MFG_PN01: JT4-1108HL; ROHS: Yes
J24 = CON_RJ45_16P: CON 16 RJ-45 RA SHLD TH G/Y LEDS 80MIL SP 554H AU 125L; AGILE_PN: 210-80866; CAD_APPROVED: Yes; HEIGHT: 14.08MM; MFG_NAME01: PULSE ENGINEERING; MFG_PN01: JT4-2004HL; ROHS: Yes
L8 L12 = BEAD: IND FER BEAD 600OHM@100MHZ 2A 25% 0805; AGILE_PN: 180-78229; CAD_APPROVED: Yes; HEIGHT: 1.05MM; MFG_NAME01: TDK; MFG_PN01: MPZ2012S601A; PART_TYPE: FERRITE\BEAD; ROHS: Yes; Tolerance: 25%
L10 = INDUCTOR: IND 600 OHM@100MHZ 0.2A 25% 0603 SMT; AGILE_PN: 180-75046; CAD_APPROVED: Yes; FPLIST: IND_0603,0603_CC; HEIGHT: 0.95MM; MFG_NAME01: MURATA; MFG_PN01: BLM18BD601SN1D; PART_TYPE: FERRITE; ROHS: Yes
L17 = BEAD: IND FER BEAD 100OHM@100MHZ 4A 25% 0805; AGILE_PN: 180-78230; CAD_APPROVED: Yes; HEIGHT: 1.05MM; MFG_NAME01: TDK; PART_TYPE: FERRITE\BEAD; ROHS: Yes; Tolerance: 25%
U8 = AQR105_BGA324: IC XCVR ETHERNET SINGLE PORT AQRATE 10GBASE-T PHY TBD FCBGA324; AGILE_PN: 312-81233; CAD_APPROVED: Yes; HEIGHT: 2.86MM; MFG_NAME01: Aquantia Corp; MFG_PN01: AQR105-B1-EG-Y; ROHS: Yes

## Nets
1V2_RST_n: R201.1 ; also on sheet 5 21
GND: C13.2 C16.2 C17.2 C18.2 C20.2 C22.2 C23.2 C24.2 C25.2 C26.2 C31.2 C33.2 C34.2 C35.2 C36.2 C42.2 C44.2 C45.2 C46.2 C47.2 C48.2 C49.2 C50.1 C51.1 C54.2 C55.2 C58.2 C64.2 C65.2 C76.2 C78.2 C167.1 C168.1 C169.1 C171.1 C172.1 C176.1 C179.1 C180.2 C185.2 C187.1 C189.2 C190.2 C191.1 C192.1 C194.1 C195.1 C196.1 C197.1 C198.2 C199.1 C200.1 C201.1 C202.1 C203.1 C204.1 C205.1 C206.1 C207.1 C209.1 C210.1 C211.1 C212.1 C213.1 C214.1 C215.1 C216.1 C218.1 C219.1 C220.1 C221.1 C222.1 C223.1 C224.1 C225.1 C226.1 C227.1 C228.1 C229.2 C230.1 C231.1 C232.1 C233.2 C234.1 C235.1 C236.1 C237.1 C238.1 C239.1 C240.1 C241.2 C242.1 C243.1 C244.1 C245.1 C246.1 C247.2 C248.1 C249.1 C250.2 C251.2 C252.1 C253.1 C254.1 C255.1 C256.1 C257.1 C258.1 C259.1 C260.1 C261.1 C262.1 C263.1 C264.1 C265.1 C266.1 C267.1 C268.1 C269.2 C270.1 C271.1 C272.1 C273.2 C274.2 C275.2 C276.1 C277.2 C278.2 C279.1 C280.1 C601.2 C602.2 C603.2 C604.2 C607.2 C608.2 D12.3(CATHODE2) D13.3(CATHODE2) J4.19 J5.19 J7.7 J8.2 R20.1 R21.2 R28.1 R30.1 R51.1 R63.1 R68.1 R72.1 R73.1 R202.2 R203.2 R205.2 R206.2 R207.1 R210.1 R211.2 R213.1 R214.1 R215.2 R219.2 R404.2 U5.49(GND) U6.49(GND) U8.A1(RG) U8.A18(RG) U8.B3(AVSS4) U8.B5(AVSS5) U8.B7(AVSS6) U8.B9(AVSS7) U8.B12(AVSS1) U8.B14(AVSS2) U8.B16(AVSS3) U8.C2(AVSS12) U8.C4(AVSS13) U8.C6(AVSS14) U8.C8(AVSS15) U8.C11(AVSS8) U8.C13(AVSS9) U8.C15(AVSS10) U8.C17(AVSS11) U8.D3(AVSS20) U8.D5(AVSS21) U8.D7(AVSS22) U8.D9(AVSS23) U8.D12(AVSS16) U8.D14(AVSS17) U8.D16(AVSS18) U8.D18(AVSS19) U8.E1(~{DC_MASTER}) U8.E4(AVSS28) U8.E6(AVSS_PLL) U8.E11(AVSS24) U8.E13(AVSS25) U8.E15(AVSS26) U8.E17(AVSS27) U8.F6(AVSS31) U8.F8(AVSS32) U8.F10(AVSS29) U8.F12(AVSS30) U8.G5(AVSS34) U8.G7(AVSS35) U8.G9(AVSS36) U8.G11(AVSS33) U8.H4(~{MDIO_1P2_SELECT}) U8.H6(AVSS39) U8.H8(AVSS40) U8.H10(AVSS37) U8.H12(AVSS38) U8.J5(VSS3) U8.J7(VSS4) U8.J9(VSS5) U8.J11(VSS1) U8.J13(VSS2) U8.K6(VSS8) U8.K8(VSS9) U8.K10(VSS6) U8.K12(VSS7) U8.L4(RG) U8.L7(VSS12) U8.L9(VSS13) U8.L11(VSS10) U8.L13(VSS11) U8.M6(VSS16) U8.M8(VSS17) U8.M10(VSS14) U8.M12(VSS15) U8.N1(VSS_SRDS1) U8.N2(VSS_SRDS2) U8.N5(VSS20) U8.N7(VSS21) U8.N9(VSS22) U8.N11(VSS18) U8.N13(VSS19) U8.P3(VSS_SRDS5) U8.P6(VSS25) U8.P8(VSS26) U8.P10(VSS23) U8.P12(VSS24) U8.P17(VSS_SRDS3) U8.P18(VSS_SRDS4) U8.R1(VSS_SRDS6) U8.R2(VSS_SRDS8) U8.R4(VSS_SRDS9) U8.R6(VSS_SRDS10) U8.R7(VSS29) U8.R9(VSS30) U8.R11(VSS27) U8.R13(VSS28) U8.R14(VSS_SRDS7) U8.T3(VSS_SRDS14) U8.T5(VSS_SRDS15) U8.T7(VSS_SRDS16) U8.T9(VSS_SRDS17) U8.T11(VSS_SRDS11) U8.T13(VSS_SRDS12) U8.T15(VSS_SRDS13) U8.U1(VSS_SRDS18) U8.U5(VSS_SRDS22) U8.U9(VSS_SRDS23) U8.U11(VSS_SRDS19) U8.U16(VSS_SRDS20) U8.U18(VSS_SRDS21) U8.V5(VSS_SRDS26) U8.V9(VSS_SRDS27) U8.V11(VSS_SRDS24) U8.V16(VSS_SRDS25) U41.4(GND) Y1.2(GND1) Y1.4(GND2) Y2.2(GND1) Y2.4(GND2) Y3.2 Y3.4 ; also on sheet 5 6 7 8 9 10 11 12 13 18 19 20 21 22 23 24
GND_EARTH: C167.2 C168.2 C169.2 C171.2 C172.2 J3.S1(GND1) J3.S2(GND2) J4.21 J4.22 J5.21 J5.22 J24.S1(GND1) J24.S2(GND2) ; also on sheet 10 13
2.5G_CMP_N: J3.15(CMS-) U8.D8(CM_N)
2.5G_CMP_P: J3.14(CMS+) U8.E8(CM_P)
2.5G_MDI0_N: J3.9(TRD1-) J24.9(TRD1-) U8.A2(A_N)
2.5G_MDI0_P: J3.8(TRD1+) J24.8(TRD1+) U8.B2(A_P)
2.5G_MDI1_N: J3.3(TRD2-) J24.3(TRD2-) U8.A4(B_N)
2.5G_MDI1_P: J3.2(TRD2+) J24.2(TRD2+) U8.B4(B_P)
2.5G_MDI2_N: J3.5(TRD3-) J24.5(TRD3-) U8.A6(C_N)
2.5G_MDI2_P: J3.4(TRD3+) J24.4(TRD3+) U8.B6(C_P)
2.5G_MDI3_N: J3.11(TRD4-) J24.11(TRD4-) U8.A8(D_N)
2.5G_MDI3_P: J3.10(TRD4+) J24.10(TRD4+) U8.B8(D_P)
12: R455.1 R456.1 ; also on sheet 22
34: R454.1 R457.1 ; also on sheet 22
56: R453.1 R458.1 ; also on sheet 22
78: R452.1 R459.1 ; also on sheet 22
AQR105_FLASH: C198.1 C218.2 C238.2 C240.2 C245.2 C246.2 J7.6 L10.1 R75.2 R76.2 R212.2 R216.2 R222.1 R392.1 R393.1 U8.E3(VDD_FLASH) U8.J3(VDD_IO1) U8.K4(VDD_IO3) U8.K16(VDD_IO2) U8.L16(VDD_IO4) U41.3(~{WP}) U41.7(~{HOLD}) U41.8(VCC) ; also on sheet 5 24
AQR105_VA12: C49.1 C54.1 C216.2 C219.2 C220.2 C223.2 C224.2 R209.1 R280.1 U8.D4(VA12_1) U8.D6(VA12_2) U8.E5(VA12_3) U8.E7(VA12_4) U8.E9(VA12_5) ; also on sheet 9 11 21 23
AQR105_VA22: C34.1 C35.1 C58.1 C76.1 C194.2 C195.2 C196.2 C197.2 C207.2 C209.2 C210.2 C211.2 C263.2 C271.2 L12.2 U8.A3(VA22_1) U8.A5(VA22_2) U8.A7(VA22_3) U8.A9(VA22_4) U8.C3(VA22_5) U8.C5(VA22_6) U8.C7(VA22_7) U8.C9(VA22_8) U8.P4(V22_SRDS1) U8.R3(V22_SRDS2) ; also on sheet 23
AQR105_VDD: C47.1 C55.1 C225.2 C226.2 C227.2 C231.2 C232.2 C239.2 C242.2 C243.2 C244.2 C248.2 C249.2 C252.2 C253.2 C254.2 C255.2 C256.2 C257.2 C258.2 C259.2 C260.2 C261.2 C262.2 C264.2 C265.2 C266.2 C267.2 C268.2 C270.2 C272.2 L8.2 L17.2 U8.J6(VDD2) U8.J8(VDD3) U8.J10(VDD29) U8.J12(VDD1) U8.K5(VDD6) U8.K7(VDD7) U8.K9(VDD8) U8.K11(VDD4) U8.K13(VDD5) U8.L6(VDD11) U8.L8(VDD12) U8.L10(VDD9) U8.L12(VDD10) U8.M7(VDD15) U8.M9(VDD16) U8.M11(VDD13) U8.M13(VDD14) U8.N6(VDD19) U8.N8(VDD20) U8.N10(VDD17) U8.N12(VDD18) U8.P5(VDD23) U8.P7(VDD24) U8.P9(VDD25) U8.P11(VDD21) U8.P13(VDD22) U8.R8(VDD28) U8.R10(VDD26) U8.R12(VDD27) ; also on sheet 23
AQR_INT_n: R228.2 R280.2 ; also on sheet 8
AQR_LED_GRN: C602.1 D14.3(CATHODE2) R26.1 U8.K1(LED0)
AQR_LED_YEL: C601.1 D14.4(CATHODE1) R24.1 U8.L1(LED1)
AQR_SPI_CS: R216.1 U8.G2(~{CE}) U41.1(~{CS})
AQR_SPI_SCLK: U8.G1(SCLK) U41.6(SCLK)
AQR_SPI_SDI: U8.F1(SIN) U41.2(SO/SIO1)
AQR_SPI_SDO: U8.F2(SOUT) U41.5(SI/SIO0)
DCDC1_3V3: R35.1 R220.1 R224.1 ; also on sheet 18 20
DCDC2_3V3: R221.1 R226.1 R395.1 R401.1 ; also on sheet 6 7 8 10 11 13 18 19 20 21 23 24
EC1_AVDD10: C204.2 C205.2 C215.2 R66.2 U5.4(AVDD10_1) U5.9(AVDD10_2) U5.47(AVDD10_3)
EC1_CLK_125M: C42.1 R50.2 R404.1 ; also on sheet 9
EC1_DVDD10: C222.2 R74.2 U5.22(DVDD10)
EC1_DVDD_3V3: C236.2 C247.1 R34.1 R57.2 R70.2 R221.2 U5.30(DVDD33)
EC1_DVDDRG: C229.1 C237.2 R217.2 U5.29(DVDD_RG)
EC1_LED0/PHYAD0: C24.1 C608.1 D12.4(CATHODE1) J4.17 R70.1 U5.35(LED0/PHYAD0)
EC1_LED1/CFG_LDO0: R31.1 R63.2 R396.1 U5.36(LED1/CFG_LDO0)
EC1_LED2/CFG_LDO1: R57.1 U5.37(LED2/CFG_LDO1)
EC1_MDIN0: J4.10 U5.3(MDIN0)
EC1_MDIN1: J4.5 U5.6(MDIN1)
EC1_MDIN2: J4.2 U5.8(MDIN2)
EC1_MDIN3: J4.9 U5.11(MDIN3)
EC1_MDIP0: J4.11 U5.2(MDIP0)
EC1_MDIP1: J4.4 U5.5(MDIP1)
EC1_MDIP2: J4.3 U5.7(MDIP2)
EC1_MDIP3: J4.8 U5.10(MDIP3)
EC1_PHY_INT_n: U5.34(~{INT}/~{PME}) ; also on sheet 8
EC1_RXC: C45.1 R65.2 ; also on sheet 9
EC1_RXC/PHYAD1: R65.1 R73.2 U5.28(RXC/PHYAD1)
EC1_RXCTL: R62.2 ; also on sheet 9
EC1_RXCTL/PHYAD2: R62.1 R72.2 U5.27(RXCTL/PHYAD2)
EC1_RXD0: R59.2 ; also on sheet 9
EC1_RXD1: R55.2 ; also on sheet 9
EC1_RXD1/CFG_MODE0: R55.1 R214.2 U5.25(RXD1/CFG_MODE0)
EC1_RXD2: R53.2 ; also on sheet 9
EC1_RXD2/CFG_MODE1: R53.1 R210.2 U5.24(RXD2/CFG_MODE1)
EC1_RXD3: R49.2 ; also on sheet 9
EC1_RXD3/CFG_MODE2: R49.1 R207.2 U5.23(RXD3/CFG_MODE2)
EC1_TXC: U5.21(TXC) ; also on sheet 9
EC1_TXCTL: U5.20(TXCTL) ; also on sheet 9
EC1_TXD0: U5.19(TXD0) ; also on sheet 9
EC1_TXD1: U5.18(TXD1) ; also on sheet 9
EC1_TXD2: U5.17(TXD2) ; also on sheet 9
EC1_TXD3: U5.16(TXD3) ; also on sheet 9
EC1_VDDREG: C235.2 C251.1 R225.2 U5.31(VDD_REG)
EMI1_MDC: R27.2 R43.2 ; also on sheet 9
EMI1_MDIO: R37.2 R46.2 ; also on sheet 9
EMI2_MDC: U8.J18(MDC) ; also on sheet 9
EMI2_MDIO: U8.L18(MDIO) ; also on sheet 9
LANEB_RX_N: U8.V6(TX_LN2_N) ; also on sheet 9
LANEB_RX_P: U8.U6(TX_LN2_P) ; also on sheet 9
LANEB_TX_N: C56.1 ; also on sheet 9
LANEB_TX_P: C57.1 ; also on sheet 9
LANED_RX_N: C30.1 ; also on sheet 9
LANED_RX_P: C37.1 ; also on sheet 9
LANED_TX_N: U6.39(HSIN) ; also on sheet 9
LANED_TX_P: U6.38(HSIP) ; also on sheet 9
LED_G-: C18.1 J3.16(LEDG1-) J24.17(GRN-1) R26.2
LED_GY+: J3.17(LEDG1+) J3.19(LEDG-) J24.18(GRN+) J24.20(GRN-2) L10.2
LED_Y-: C16.1 J3.18(LEDY-) J24.19(YEL-) R24.2
RESET: U5.13(~{PHYRST}) U6.13(~{PHYRST}) ; also on sheet 7 8 18 21
SGMII_AVDD10: C199.2 C200.2 C214.2 R64.2 U6.4(AVDD10_1) U6.9(AVDD10_2) U6.47(AVDD10_3)
SGMII_DVDD10: C221.2 R71.2 U6.22(DVDD10)
SGMII_DVDD_3V3: C230.2 C241.1 R58.2 R218.2 R220.2 U6.30(DVDD33)
SGMII_DVDDRG: C228.2 C233.1 R56.2 R67.2 R69.2 U6.29(DVDD_RG)
SGMII_LED0/PHYAD0: C20.1 C603.1 D13.4(CATHODE1) J5.17 R58.1 U6.35(LED0/PHYAD0)
SGMII_LED1/CFG_LDO0: R32.1 R213.2 R394.1 U6.36(LED1/CFG_LDO0)
SGMII_LED2/CFG_LDO1: R218.1 U6.37(LED2/CFG_LDO1)
SGMII_MDIN0: J5.10 U6.3(MDIN0)
SGMII_MDIN1: J5.5 U6.6(MDIN1)
SGMII_MDIN2: J5.2 U6.8(MDIN2)
SGMII_MDIN3: J5.9 U6.11(MDIN3)
SGMII_MDIP0: J5.11 U6.2(MDIP0)
SGMII_MDIP1: J5.4 U6.5(MDIP1)
SGMII_MDIP2: J5.3 U6.7(MDIP2)
SGMII_MDIP3: J5.8 U6.10(MDIP3)
SGMII_PHY_INT_n: U6.34(~{INT}/~{PME}) ; also on sheet 8
SGMII_RXC/PHYAD1: R67.1 U6.28(RXC/PHYAD1)
SGMII_RXCTL/PHYAD2: R68.2 U6.27(RXCTL/PHYAD2)
SGMII_RXD1/CFG_MODE0: R69.1 U6.25(RXD1/CFG_MODE0)
SGMII_RXD2/CFG_MODE1: R56.1 U6.24(RXD2/CFG_MODE1)
SGMII_RXD3/CFG_MODE2: R51.2 U6.23(RXD3/CFG_MODE2)
SGMII_VDDREG: C234.2 C250.1 R223.2 U6.31(VDD_REG)
TRCT: C176.2 C179.2 C180.1 C185.1 C187.2 C191.2 C192.2 J3.1(TRCT2) J3.6(TRCT3) J3.7(TRCT1) J3.12(TRCT4) J3.13(CMCT) J24.1(TRCT2) J24.6(TRCT3) J24.7(TRCT1) J24.12(TRCT4)
N24185665: C57.2 U8.U4(RX_LN2_P)
N24185672: C56.2 U8.V4(RX_LN2_N)
N24186431: R222.2 U8.N17(~{RX_DC_RST})
N24186507: R209.2 U8.F5(TX_EN)
N24186703: R201.2 U8.J4(~{RST})
N24186832: C31.1 U8.F18(XTAL_I) Y3.1
N24187101: R52.2 U8.G18(XTAL_O)
N24187104: J7.1 U8.L14(TDI)
N24187111: J7.2 U8.M16(TMS)
N24187118: J7.3 U8.K14(TCK)
N24187125: J7.4 R202.1 U8.M15(~{TRST})
N24187168: J7.5 U8.L15(TDO)
N24187336: R20.2 U8.A10(RREF_BG)
N24187387: R203.1 U8.F17(~{XTAL_SELECT})
N24187390: R21.1 U8.G13(50M_CLK_TERM)
N24187475: R212.1 U8.H3(~{RST_OUT})
N24187514: J8.3 R75.1 U8.H18(SMB_DAT)
N24187517: J8.1 R76.1 U8.H17(SMB_CLK)
N24187752: R219.1 U8.K15(ADDR0)
N24187759: R205.1 U8.J15(ADDR1)
N24187766: R215.1 U8.J16(ADDR2)
N24187780: R211.1 U8.H16(ADDR3)
N24187787: R206.1 U8.G17(ADDR4)
N24189801: R228.1 U8.K18(~{INT})
N24194949: C64.1 C78.1 C269.1 C275.1 C276.2 C277.1 C278.1 C280.2 L17.1 U8.R5(VDD_SRDS1) U8.T8(VDD_SRDS4) U8.T10(VDD_SRDS2) U8.T12(VDD_SRDS3)
N24197224: C65.1 C273.1 C274.1 C279.2 U8.T4(P0_VREG_SRDS1) U8.T6(P0_VREG_SRDS2)
N24197929: C13.1 C212.2 L8.1 U8.E10(AFE_DVDD)
N24198270: C17.1 C213.2 L12.1 U8.E18(VA22_XTAL)
N24288324: C203.2 C206.2 R225.1 R226.2 U5.1(AVDD33) U5.12(AVDD33_2)
N24289313: C48.1 C51.2 L14.2 R66.1 R74.1
N24289334: L14.1 U5.32(REG_OUT)
N24291582: C36.1 R40.1 U5.45(XTAL_IN) Y2.1
N24291591: C26.1 R40.2 U5.46(XTAL_OUT/EXT_CLK) Y2.3
N24291955: R59.1 R217.1 U5.26(RXD0/RXDLY)
N24292790: R30.2 U5.48(RSET)
N24294529: D12.2(ANODE1) R401.2
N24294558: C607.1 D12.1(ANODE2) R396.2
N24301989: C201.2 C202.2 R223.1 R224.2 U6.1(AVDD33) U6.12(AVDD33_2)
N24302177: C46.1 C50.2 L15.2 R64.1 R71.1
N24302183: L15.1 U6.32(REG_OUT)
N24302493: C33.1 R39.1 U6.45(XTAL_IN) Y1.1
N24302533: C25.1 R39.2 U6.46(XTAL_OUT/EXT_CLK) Y1.3
N24302727: R28.2 U6.48(RSET)
N24303060: D13.2(ANODE1) R395.2
N24303062: C604.1 D13.1(ANODE2) R394.2
N24307470: C37.2 U6.40(HSOP)
N24307585: C30.2 U6.41(HSON)
N24322101: R50.1 U5.44(CLKOUT)
N24616249: C44.1 R52.1 Y3.3
N25139524: D14.2(ANODE1) R393.2
N25139526: D14.1(ANODE2) R392.2
N25171285: R27.1 U5.14(MDC)
N25171337: R43.1 U6.14(MDC)
N25171340: R46.1 U6.15(MDIO)
N25235874: C22.1 J4.20 R31.2
N25235936: C189.1 J4.1 J4.6 J4.7 J4.12
N25236971: J4.18 R34.2
N25238548: C190.1 J5.1 J5.6 J5.7 J5.12
N25238664: J5.18 R35.2
N25239505: C23.1 J5.20 R32.2
N25276538: R37.1 U5.15(MDIO)
N26747830: J24.16 R452.2
N26747833: J24.15 R453.2
N26747836: J24.14 R454.2
N26747839: J24.13 R455.2
N26748165: J4.13 R456.2
N26748168: J4.14 R457.2
N26748171: J4.15 R458.2
N26748174: J4.16 R459.2

Not connected (* = marked no-connect by the designer): J5 13* 14* 15* 16*; U5 33(NC)* 38(HSIP)* 39(HSIN)* 40(HSOP)* 41(HSON)* 42(HSOP_CLK)* 43(HSON_CLK)*; U6 16(TXD3)* 17(TXD2)* 18(TXD1)* 19(TXD0)* 20(TXCTL)* 21(TXC)* 26(RXD0/RXDLY)* 33(NC)* 42(HSOP_CLK)* 43(HSON_CLK)* 44(CLKOUT)*; U8 A11(NC)* A12(NC)* A13(NC)* A14(NC)* A15(NC)* A16(NC)* A17(NC)* B1(RNC)* B10(NC)* B11(NC)* B13(NC)* B15(NC)* B17(NC)* B18(NC)* C1(CLK_1588_N) C10(RNC)* C12(NC)* C14(NC)* C16(NC)* C18(NC)* D1(CLK_1588_P) D2(CLKO_50M_A) D10(RNC)* D11(NC)* D13(NC)* D15(NC)* D17(NC)* E2(RNC)* E12(NC)* E14(NC)* E16(NC)* F3(TDIO_N) F4(RNC)* F7(NC)* F9(NC)* F11(NC)* F13(RNC)* F14(NC)* F15(RNC)* F16(RNC)* G3(TDIO_P) G4(RNC)* G6(NC)* G8(NC)* G10(NC)* G12(NC)* G14(RNC)* G15(NC)* G16(RNC)* H1(RX_DC_DATA) H2(~{TX_DC_RST}) H5(NC)* H7(NC)* H9(NC)* H11(NC)* H13(NC)* H14(RNC)* H15(RNC)* J1(RX_DC_CLK) J2(RX_DC_SOF) J14(RNC)* J17(NC)* K2(NC)* K3(WAKE) K17(NC)* L2(NC)* L3(~{PERST}) L5(RNC)* L17(NC)* M1(LED2)* M2(NC)* M3(NC)* M4(RNC)* M5(RNC)* M14(RNC)* M17(TX_DC_DATA) M18(TX_DC_SOF) N3(NC)* N4(RNC)* N14(RNC)* N15(1588_SYNC) N16(RNC)* N18(TX_DC_CLK) P1(RX_LN0_N)* P2(RX_LN0_P)* P14(RNC)* P15(NC)* P16(RNC)* R15(NC)* R16(NC)* R17(NC)* R18(NC)* T1(TX_LN0_N)* T2(TX_LN0_P)* T14(RNC)* T16(NC)* T17(NC)* T18(NC)* U2(RX_LN1_P)* U3(TX_LN1_P)* U7(RX_LN3_P)* U8(TX_LN3_P)* U10(NC)* U12(NC)* U13(NC)* U14(NC)* U15(NC)* U17(NC)* V1(RNC)* V2(RX_LN1_N)* V3(TX_LN1_N)* V7(RX_LN3_N)* V8(TX_LN3_N)* V10(NC)* V12(NC)* V13(NC)* V14(NC)* V15(NC)* V17(NC)* V18(RNC)*

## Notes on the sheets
sheet 14
- RGMII
- LABEL NAME: ETH1
- 100ohm match
- add pull up resistor on RXDLY pin of the PHY to
  add 2ns delay to RXC for RXD latching
  Enabling TXDLY can be done via register
  setting:Page 0xd08, reg17, bit[8]=1
- PHY CONFIGURATION:
- LED1(Green): LINK
  LED0(Yellow): ACTIVE
  PHY Address PHYAD[2:0]
  1  3'b001
- RGMII Power Source CFG_LDO[1:0]
  External 3.3V 2'b00
  Internal 2.5V 2'b01
  Internal 1.8V 2'b10 (default)
  Internal 1.5V 2'b11
- UTP<<=>>RGMII
   CFG_MODE[2:0] 3'b000
- ACTIVE
- Link
sheet 15
- PHY 3V3 rise time should between 0.5ms~100ms
  PHY internal LDO works after RESET deassert 50ms.
- LABEL NAME:ETH2
- 100ohm match
- SGMII 1G
- ACTIVE
- Link
- PHY CONFIGURATION:
- LED1(Green): LINK
  LED0(Yellow): ACTIVE
- RGMII Power Source CFG_LDO[1:0]
  External 3.3V 2'b00
  Internal 2.5V 2'b01
  Internal 1.8V 2'b10 (default)
  Internal 1.5V 2'b11
- UTP<<=>>SGMII
  CFG_MODE[2:0] 3'b011
- PHY Address PHYAD[2:0]
  3 3'b011
sheet 16
- 100ohm match
- PHY ADDR 0X02
- 100ohm match
- Keep the clock trace as short
  as possible to reduce the loop area.
  Route parallel ground islands on
  each side of the clock traces with
  large number of vias on the islands
  Route the clock signal in between
  Ground and Power planes
- 100ohm match
- LANE 2 WORKS ON 2.5G SGMII MODE
  PHY ADDRESS IS 0X02,EMI2
  PHY INTERRUPT TO IRQ3
sheet 17
- All the Caps should be placed under
  silicon and close to respective pin
  ASAP
- The 1.2V and 2.1V supplies are
   primarily analog supplies, and
  as such, all of the different analog
  power supply domains must be
  kept very quiet and separated
  via ferrite beads. These analog
  supplies must be kept away from
  the VDD and digital grounds to prevent
  capacitive coupling of noise into the
   analog circuitry. We recommend
  designing the PCB layer stack-up
  with ground shield planes above
  and below the analog supplies layer.
  The 2.1V rail for the 28nm PHYs
  requires a clean supply to ensure
   systems pass FCC
- DCDC_V85
  Place the large bulk capacitors for all
  of the rails around the periphery
  of the PHY. These are designed
  to source charge for the smaller
   decoupling capacitors and to
  smooth out ripple from the buck
   conversion process in the power regulators.
  Run the VDD rail and Ground on internal planes
  Use via-in-pad technology to
  maximize available area for decoupling
  capacitance.
  Use epoxy-filled vias to prevent
  wicking during the reflow process
  Use 15 mils traces and 12 mils vias
   for the power supply breakouts.
- ACTIVE
- When routing LED signals to the cable
  connector or front panel, avoid running
   the traces too close in parallel with the
  XFI or BASE-T MDI signals on the same
   or adjacent layer. The separation must
  be at least 10x of the MDI signal trace
   width. If the LED signals need to run
   near the MDI traces, rout them on
   another layer that is separated by at
   least one power or ground layer
- Link
- Dual Footprint:
  overlap J3 and J24 in layout, only one part will be populated
- 100ohm match
